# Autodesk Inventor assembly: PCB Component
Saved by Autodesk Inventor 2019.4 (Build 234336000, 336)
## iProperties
Created: 2020-04
Part Number: PCB Component
Document SubType Name: Assembly
Designer: Administrator
Title: PCB Component
Author: Administrator
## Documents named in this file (12)
- c:\worker\convert-fusion-r02\tmp\job-1\80\output\files\d47cb518-47af-42ea-ab47-d9c345b547b9\PCB Component.iam
- c:\worker\convert-fusion-r02\tmp\job-1\80\output\files\d47cb518-47af-42ea-ab47-d9c345b547b9\Board.ipt
- c:\worker\convert-fusion-r02\tmp\job-1\80\output\files\d47cb518-47af-42ea-ab47-d9c345b547b9\1X04.ipt
- c:\worker\convert-fusion-r02\tmp\job-1\80\output\files\d47cb518-47af-42ea-ab47-d9c345b547b9\1X19.ipt
- c:\worker\convert-fusion-r02\tmp\job-1\80\output\files\d47cb518-47af-42ea-ab47-d9c345b547b9\1X06.ipt
- c:\worker\convert-fusion-r02\tmp\job-1\80\output\files\d47cb518-47af-42ea-ab47-d9c345b547b9\1X02.ipt
- c:\worker\convert-fusion-r02\tmp\job-1\80\output\files\d47cb518-47af-42ea-ab47-d9c345b547b9\1X03.ipt
- c:\worker\convert-fusion-r02\tmp\job-1\80\output\files\d47cb518-47af-42ea-ab47-d9c345b547b9\R0805.ipt
- c:\worker\convert-fusion-r02\tmp\job-1\80\output\files\d47cb518-47af-42ea-ab47-d9c345b547b9\DSN-1504.ipt
- c:\worker\convert-fusion-r02\tmp\job-1\80\output\files\d47cb518-47af-42ea-ab47-d9c345b547b9\DO27-15.ipt
- c:\worker\convert-fusion-r02\tmp\job-1\80\output\files\d47cb518-47af-42ea-ab47-d9c345b547b9\MODULE_ESP32-DEVKITC.ipt
- c:\worker\convert-fusion-r02\tmp\job-1\80\output\files\d47cb518-47af-42ea-ab47-d9c345b547b9\DIL16.ipt
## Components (17 placed, 17 different names)
1. Board:1
2. 1X04:MPU9250
3. 1X04:VL53L0X
4. 1X19:JP6
5. 1X06:MOT3_HD
6. 1X06:MOT2_HD
7. 1X06:MOT1_HD
8. 1X02:JP1
9. 1X03:JP2
10. R0805:R1
11. R0805:R2
12. DSN-1504:U$1
13. DO27-15:D2
14. MODULE_ESP32-DEVKITC:U1
15. 1X19:JP7
16. DIL16:MOT1-2_H
17. DIL16:MOT3_H
